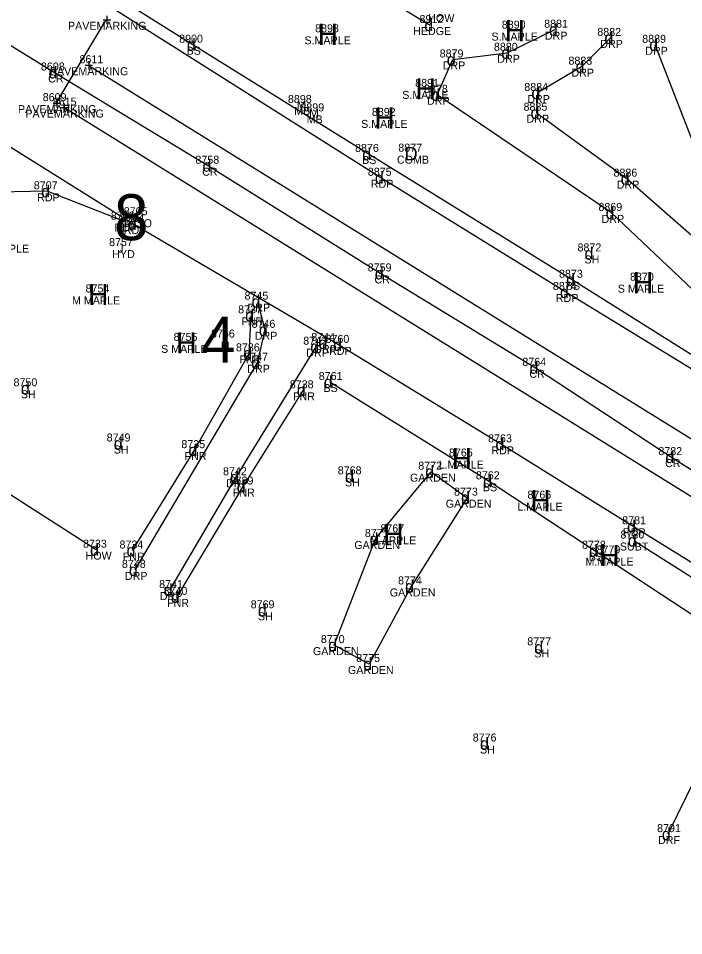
# Model space of a CAD drawing. Extents: x 69415 to 80913, y 7576 to 15059.
# Drawn here: x 77718.2 to 77884.6, y 12956.1 to 13185.4 of the extents above; entities that cross this region are included whole.
import ezdxf

# ---------------------------------------------------------------- set-up
doc = ezdxf.new("R2010")
doc.units = 0
for name, color, linetype in [('Level 11', 7, 'Continuous'), ('Level 12', 7, 'Continuous'), ('Level 13', 7, 'Continuous'), ('Level 14', 7, 'Continuous'), ('Level 15', 7, 'Continuous'), ('Level 45', 7, 'Continuous'), ('Level 46', 7, 'Continuous'), ('Level 47', 7, 'Continuous'), ('Level 48', 7, 'Continuous')]:
    doc.layers.add(name, color=color, linetype=linetype)

msp = doc.modelspace()

# ---------------------------------------------------------------- linework, layer by layer
at = {"layer": 'Level 11'}
for p, q in [((77808.85, 13145.56), (77725.76, 13198.05)), ((77840.48, 13176.81), (77852.39, 13182.59)), ((77866.25, 13180.53), (77859.04, 13173.33)), ((77897.68, 13126.63), (77877.49, 13178.8)), ((77679.4, 13176.21), (77747.08, 13134)), ((77826.83, 13175.14), (77840.48, 13176.81)), ((77822.91, 13166.3), (77826.83, 13175.14)), ((77859.04, 13173.33), (77847.99, 13166.76)), ((77866.57, 13136.78), (77822.91, 13166.3)), ((77847.99, 13166.76), (77847.8, 13161.82)), ((77847.8, 13161.82), (77870.35, 13145.35)), ((77855.14, 13117.01), (77808.85, 13145.56)), ((77870.35, 13145.35), (77895.03, 13123.77)), ((77725.38, 13142.18), (77706.06, 13141.84)), ((77744.71, 13134.61), (77725.38, 13142.18)), ((77899.89, 13105.23), (77866.57, 13136.78)), ((77747.08, 13134), (77798.4, 13103.8)), ((77907.51, 13084.89), (77855.14, 13117.01)), ((77778.01, 13114.6), (77779.83, 13107.56)), ((77779.83, 13107.56), (77777.94, 13099.33)), ((77792.7, 13103.33), (77794.71, 13104.28)), ((77772.63, 13070.7), (77792.7, 13103.33)), ((77798.4, 13103.8), (77838.99, 13078.94)), ((77777.94, 13099.33), (77747.34, 13047.54)), ((77838.99, 13078.94), (77871.92, 13058.45)), ((77756.09, 13042.51), (77772.63, 13070.7)), ((77871.92, 13058.45), (77911.53, 13033.98)), ((77895.05, 13010.92), (77880.63, 12981.5))]:
    msp.add_line(p, q, dxfattribs=at)
at = {"layer": 'Level 12'}
for p, q in [((77775.93, 13101.67), (77776.42, 13111.16)), ((77762.21, 13077.48), (77775.93, 13101.67)), ((77789.33, 13092.43), (77774.29, 13068.38)), ((77746.74, 13052.39), (77762.21, 13077.48)), ((77807.54, 13055.28), (77821.46, 13072.1)), ((77821.46, 13072.1), (77830.41, 13065.6)), ((77774.29, 13068.38), (77757.84, 13040.8)), ((77830.41, 13065.6), (77816.41, 13043.41)), ((77797.19, 13028.75), (77807.54, 13055.28)), ((77816.41, 13043.41), (77805.95, 13024.02)), ((77805.95, 13024.02), (77797.19, 13028.75))]:
    msp.add_line(p, q, dxfattribs=at)
at = {"layer": 'Level 13'}
msp.add_line((77710.94, 13069.76), (77737.61, 13052.61), dxfattribs=at)
at = {"layer": 'Level 14'}
msp.add_line((77810.59, 13190.24), (77821.22, 13183.74), dxfattribs=at)
at = {"layer": 'Level 15'}
msp.add_line((77872.12, 13054.89), (78265.18, 12804.76), dxfattribs=at)
at = {"layer": 'Level 45'}
for p, q in [((77727.66, 13164.22), (77740.17, 13185.06)), ((77735.64, 13173.7), (78075.52, 12963.26)), ((77919.58, 13045.27), (77729.52, 13163.12))]:
    msp.add_line(p, q, dxfattribs=at)
at = {"layer": 'Level 48'}
for p, q in [((77679.14, 13201.47), (77727.21, 13171.88)), ((77761.83, 13178.82), (77735.74, 13195.16)), ((77805.71, 13151.52), (77761.83, 13178.82)), ((77727.21, 13171.88), (77765.73, 13148.57)), ((77856.67, 13120.07), (77805.71, 13151.52)), ((77765.73, 13148.57), (77808.82, 13121.65)), ((77808.82, 13121.65), (77847.55, 13098.06)), ((77906.36, 13088.84), (77856.67, 13120.07)), ((77847.55, 13098.06), (77881.52, 13075.74)), ((77796.06, 13094.52), (77835.93, 13069.7)), ((77881.52, 13075.74), (77920.88, 13051.04)), ((77835.93, 13069.7), (77862.42, 13052.33)), ((77862.42, 13052.33), (77898.19, 13028.79))]:
    msp.add_line(p, q, dxfattribs=at)

# ---------------------------------------------------------------- texts
at = {"layer": 'Level 12'}
for p in [(77787.77, 13162.66), (77790.89, 13160.56)]:
    msp.add_text('M', height=2.2, dxfattribs=at).set_placement(p)
at = {"layer": 'Level 14'}
for p in [(77839.8, 13179.7), (77793.02, 13178.78), (77817.48, 13165.14), (77807.21, 13157.88), (77871.86, 13116.69), (77735.6, 13113.74), (77757.63, 13101.64), (77826.54, 13072.73), (77846.23, 13062.2), (77809.4, 13053.79), (77863.43, 13048.49)]:
    msp.add_text('H', height=5.3, dxfattribs=at).set_placement(p)
at = {"layer": 'Level 15'}
for s, height, p in [('D', 3.4, (77814.78, 13149.89)), ('8', 11.5, (77742.14, 13129.95)), ('J', 2.26, (77743, 13126.85)), ('4', 11.5, (77763.93, 13099.37))]:
    msp.add_text(s, height=height, dxfattribs=at).set_placement(p)
at = {"layer": 'Level 46'}
for s, p in [('PAVEMARKING', (77730.59, 13182.56)), ('8912', (77818.52, 13184.24)), ('HOW', (77820.7, 13184.47)), ('8890', (77839.1, 13182.85)), ('8881', (77849.7, 13183.09)), ('8893', (77792.41, 13181.93)), ('HEDGE', (77816.92, 13181.24)), ('8882', (77862.99, 13181.03)), ('8900', (77758.4, 13179.32)), ('S.MAPLE', (77789.73, 13178.93)), ('S.MAPLE', (77836.51, 13179.85)), ('DRP', (77849.88, 13180.09)), ('DRP', (77863.73, 13178.03)), ('8889', (77874.22, 13179.3)), ('BS', (77760.27, 13176.32)), ('8879', (77823.56, 13175.64)), ('8880', (77837.13, 13177.31)), ('DRP', (77874.98, 13176.3)), ('8611', (77733.47, 13174.2)), ('DRP', (77837.97, 13174.31)), ('8883', (77855.78, 13173.83)), ('8608', (77723.82, 13172.38)), ('PAVEMARKING', (77726.06, 13171.2)), ('DRP', (77824.32, 13172.64)), ('CR', (77725.64, 13169.38)), ('DRP', (77856.53, 13170.83)), ('8891', (77817.44, 13168.29)), ('8878', (77819.65, 13166.8)), ('8884', (77844.73, 13167.26)), ('8609', (77724.27, 13164.72)), ('8898', (77785.61, 13164.26)), ('S.MAPLE', (77814.19, 13165.29)), ('DRP', (77845.48, 13164.26)), ('8615', (77726.78, 13163.62)), ('8899', (77788.72, 13162.16)), ('DRP', (77820.39, 13163.8)), ('8885', (77844.54, 13162.32)), ('PAVEMARKING', (77718.08, 13161.72)), ('PAVEMARKING', (77719.94, 13160.62)), ('MB', (77787.18, 13161.26)), ('8892', (77806.6, 13161.03)), ('MB', (77790.29, 13159.16)), ('S.MAPLE', (77803.92, 13158.03)), ('DRP', (77845.29, 13159.32)), ('8876', (77802.39, 13152.02)), ('8877', (77813.22, 13152.09)), ('8758', (77762.47, 13149.07)), ('BS', (77804.15, 13149.02)), ('COMB', (77812.87, 13149.09)), ('CR', (77764.16, 13146.07)), ('8875', (77805.59, 13146.06)), ('8886', (77867.04, 13145.85)), ('8707', (77722.04, 13142.68)), ('RDP', (77806.34, 13143.06)), ('DRP', (77867.84, 13142.85)), ('RDP', (77722.87, 13139.68)), ('8869', (77863.26, 13137.28)), ('8706', (77741.31, 13135.11)), ('8704', (77743.74, 13134.5)), ('8705', (77744.55, 13136.2)), ('DRP', (77864.06, 13134.28)), ('RDP', (77742.2, 13132.11)), ('WSO', (77745.22, 13133.2)), ('RDP', (77744.57, 13131.5)), ('8757', (77740.87, 13128.48)), ('M MAPLE', (77708.83, 13126.85)), ('HYD', (77741.65, 13125.48)), ('8872', (77858.04, 13127.15)), ('SH', (77859.79, 13124.15)), ('8759', (77805.56, 13122.15)), ('8873', (77853.41, 13120.57)), ('CR', (77807.26, 13119.15)), ('8870', (77871.17, 13119.84)), ('8754', (77734.99, 13116.89)), ('8874', (77851.88, 13117.51)), ('BS', (77855.11, 13117.57)), ('S MAPLE', (77868.12, 13116.84)), ('M MAPLE', (77731.6, 13113.89)), ('8745', (77774.75, 13115.1)), ('RDP', (77852.62, 13114.51)), ('8737', (77773.16, 13111.66)), ('DRP', (77775.5, 13112.1)), ('FNR', (77773.96, 13108.66)), ('8746', (77776.51, 13108.06)), ('8755', (77757.02, 13104.79)), ('8756', (77766.36, 13105.62)), ('DRP', (77777.32, 13105.06)), ('8744', (77791.45, 13104.78)), ('LI', (77768.78, 13102.62)), ('8736', (77772.61, 13102.17)), ('8743', (77789.44, 13103.83)), ('8760', (77795.01, 13104.3)), ('S MAPLE', (77753.88, 13101.79)), ('8747', (77774.68, 13099.83)), ('DRP', (77790.19, 13100.83)), ('DRP', (77792.19, 13101.78)), ('RDP', (77795.89, 13101.3)), ('FNR', (77773.46, 13099.17)), ('8764', (77844.24, 13098.56)), ('DRP', (77775.43, 13096.83)), ('CR', (77845.98, 13095.56)), ('8750', (77716.97, 13093.45)), ('8761', (77793.32, 13095.02)), ('8738', (77786.07, 13092.93)), ('BS', (77794.5, 13092.02)), ('SH', (77718.8, 13090.45)), ('FNR', (77786.87, 13089.93)), ('8749', (77740.27, 13079.64)), ('8763', (77835.68, 13079.44)), ('8735', (77758.95, 13077.98)), ('SH', (77742.03, 13076.64)), ('FNR', (77759.75, 13074.98)), ('8765', (77825.88, 13075.88)), ('RDP', (77836.48, 13076.44)), ('8782', (77878.26, 13076.24)), ('8772', (77818.2, 13072.6)), ('L.MAPLE', (77823.3, 13072.88)), ('CR', (77879.95, 13073.24)), ('8742', (77769.37, 13071.2)), ('8768', (77798.07, 13071.43)), ('8762', (77832.62, 13070.2)), ('DRP', (77770.12, 13068.2)), ('8739', (77771.02, 13068.88)), ('SH', (77799.86, 13068.43)), ('GARDEN', (77816.13, 13069.6)), ('FNR', (77771.82, 13065.88)), ('8773', (77827.15, 13066.1)), ('BS', (77834.37, 13067.2)), ('8766', (77845.52, 13065.35)), ('GARDEN', (77825.08, 13063.1)), ('L.MAPLE', (77842.99, 13062.35)), ('8781', (77869.22, 13058.95)), ('8767', (77808.74, 13056.94)), ('8771', (77804.85, 13055.78)), ('8780', (77868.78, 13055.39)), ('RDP', (77869.4, 13055.95)), ('8733', (77734.35, 13053.11)), ('8734', (77743.48, 13052.89)), ('GARDEN', (77802.21, 13052.78)), ('M.APPLE', (77806.11, 13053.94)), ('8778', (77859.16, 13052.83)), ('SUBT', (77868.62, 13052.39)), ('HOW', (77734.99, 13050.11)), ('FNR', (77744.28, 13049.89)), ('BS', (77860.86, 13049.83)), ('8779', (77862.81, 13051.64)), ('8748', (77744.08, 13048.04)), ('M.MAPLE', (77860.02, 13048.64)), ('DRP', (77744.83, 13045.04)), ('8741', (77753.39, 13043.01)), ('8774', (77813.15, 13043.91)), ('8740', (77754.49, 13041.3)), ('GARDEN', (77811.08, 13040.91)), ('DRP', (77753.58, 13040.01)), ('FNR', (77755.37, 13038.3)), ('8769', (77776.29, 13037.95)), ('SH', (77778.1, 13034.95)), ('8770', (77793.84, 13029.25)), ('8777', (77845.47, 13028.67)), ('GARDEN', (77791.86, 13026.25)), ('8775', (77802.69, 13024.52)), ('SH', (77847.22, 13025.67)), ('GARDEN', (77800.62, 13021.52)), ('8776', (77831.83, 13004.65)), ('SH', (77833.64, 13001.65)), ('8791', (77877.94, 12982)), ('DRF', (77878.16, 12979))]:
    msp.add_text(s, height=2, dxfattribs=at).set_placement(p)
at = {"layer": 'Level 47'}
for s, p in [('+', (77739.19, 13183.56)), ('d', (77819.72, 13182.24)), ('d', (77850.89, 13181.09)), ('d', (77864.75, 13179.03)), ('d', (77760.33, 13177.32)), ('d', (77875.99, 13177.3)), ('d', (77838.98, 13175.31)), ('d', (77825.33, 13173.64)), ('d', (77725.71, 13170.38)), ('+', (77734.66, 13172.2)), ('d', (77857.54, 13171.83)), ('d', (77846.49, 13165.26)), ('d', (77821.41, 13164.8)), ('+', (77726.68, 13162.72)), ('+', (77728.54, 13161.62)), ('d', (77846.3, 13160.32)), ('d', (77804.21, 13150.02)), ('d', (77764.23, 13147.07)), ('d', (77807.35, 13144.06)), ('d', (77868.85, 13143.85)), ('d', (77723.88, 13140.68)), ('d', (77743.21, 13133.11)), ('d', (77865.07, 13135.28)), ('d', (77745.58, 13132.5)), ('d', (77859.8, 13125.15)), ('d', (77807.32, 13120.15)), ('d', (77855.17, 13118.57)), ('d', (77853.64, 13115.51)), ('d', (77776.51, 13113.1)), ('d', (77774.92, 13109.66)), ('d', (77778.33, 13106.06)), ('d', (77791.2, 13101.83)), ('d', (77793.21, 13102.78)), ('d', (77796.9, 13102.3)), ('d', (77774.43, 13100.17)), ('d', (77776.44, 13097.83)), ('d', (77846.05, 13096.56)), ('d', (77794.56, 13093.02)), ('d', (77718.81, 13091.45)), ('d', (77787.83, 13090.93)), ('d', (77742.04, 13077.64)), ('d', (77760.71, 13075.98)), ('d', (77837.49, 13077.44)), ('d', (77880.02, 13074.24)), ('d', (77771.13, 13069.2)), ('d', (77799.88, 13069.43)), ('d', (77819.96, 13070.6)), ('d', (77772.79, 13066.88)), ('d', (77834.43, 13068.2)), ('d', (77828.91, 13064.1)), ('d', (77870.42, 13056.95)), ('d', (77806.04, 13053.78)), ('d', (77870.62, 13053.39)), ('d', (77736.11, 13051.11)), ('d', (77745.24, 13050.89)), ('d', (77860.92, 13050.83)), ('d', (77745.84, 13046.04)), ('d', (77814.91, 13041.91)), ('d', (77754.59, 13041.01)), ('d', (77756.34, 13039.3)), ('d', (77778.11, 13035.95)), ('d', (77795.69, 13027.25)), ('d', (77847.23, 13026.67)), ('d', (77804.45, 13022.52)), ('d', (77833.65, 13002.65)), ('d', (77879.13, 12980))]:
    msp.add_text(s, height=3, dxfattribs=at).set_placement(p)

doc.saveas('drawing.dxf')
